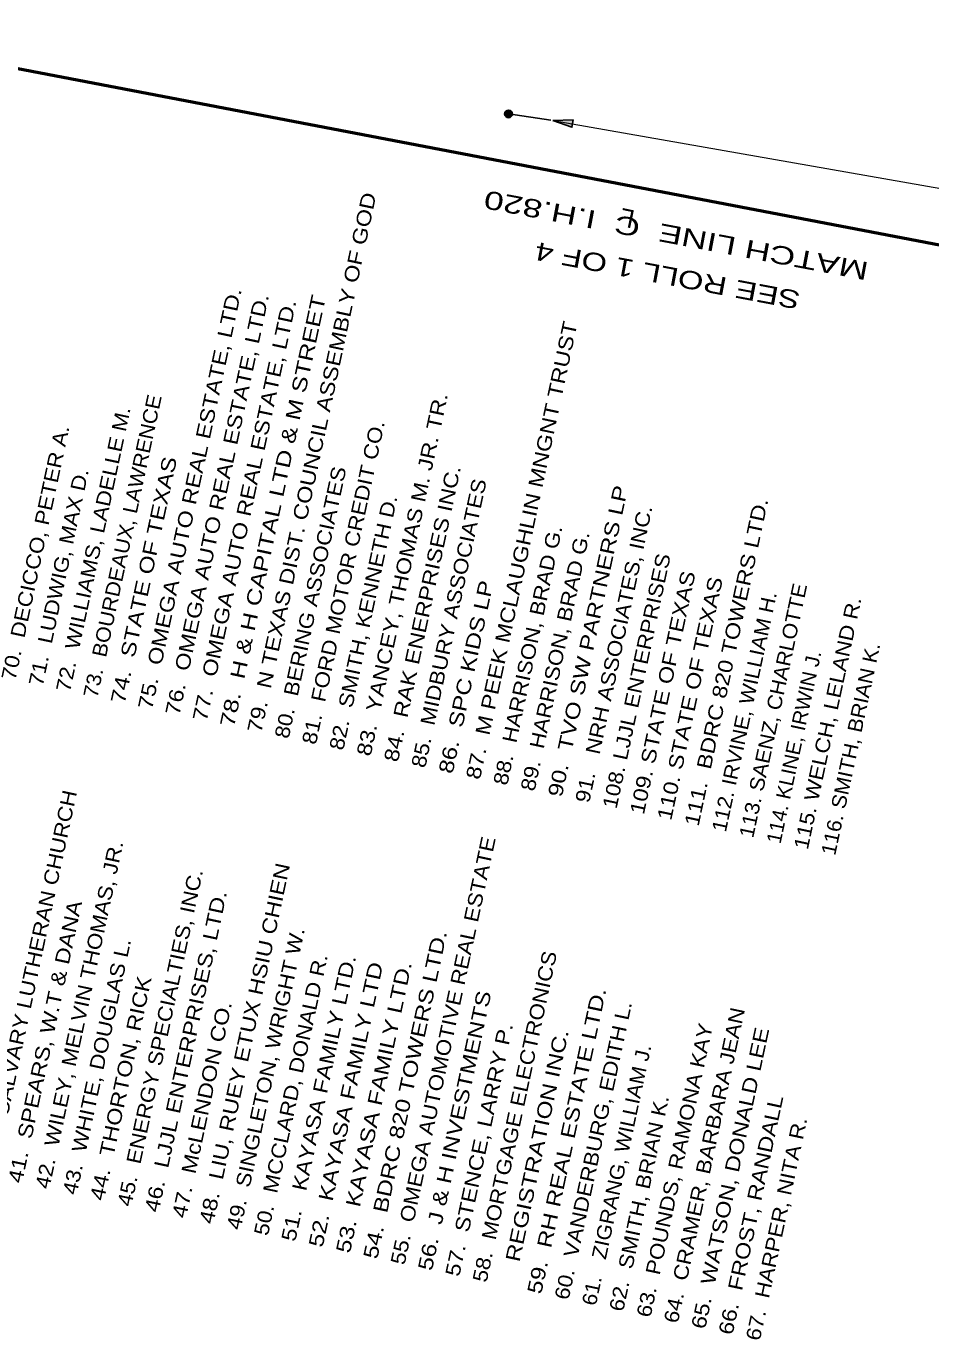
# Model space of a CAD drawing. Extents: x 2363411 to 2369702, y 6977197 to 6988655.
# Drawn here: x 2364093 to 2364967, y 6977941 to 6979210 of the extents above; entities that cross this region are included whole.
import ezdxf
from ezdxf.enums import TextEntityAlignment as Align

# ---------------------------------------------------------------- set-up
doc = ezdxf.new("R2010")
doc.units = 0
doc.header["$LTSCALE"] = 5.6
for name, color, linetype, lineweight in [('1', 7, 'Continuous', 25), ('18', 7, 'Continuous', 35), ('61', 7, 'Continuous', 25)]:
    doc.layers.add(name, color=color, linetype=linetype, lineweight=lineweight)

msp = doc.modelspace()

# ---------------------------------------------------------------- hatches: boundary and pattern name
at = {"layer": '1'}
for points in [[(2364561.269, 6979128.576, 1), (2364556.971, 6979122.474, 1)], [(2364602.052, 6979119.271), (2364620.433, 6979112.666), (2364621.582, 6979119.777)]]:
    msp.add_hatch(color=256, dxfattribs=at).paths.add_polyline_path(points)

# ---------------------------------------------------------------- linework, layer by layer
at = {"layer": '1', "lineweight": 53}
msp.add_line((2365678.349, 6978864.266), (2363870.127, 6979210.247), dxfattribs=at)
at = {"layer": '1'}
msp.add_line((2364559.12, 6979125.526), (2364599.897, 6979119.61), dxfattribs=at)
at = {"layer": '1', "lineweight": 13}
msp.add_line((2364602.343, 6979119.226), (2365303.581, 6978996.095), dxfattribs=at)
at = {"layer": '1'}
msp.add_lwpolyline([(2364602.052, 6979119.271), (2364620.433, 6979112.666), (2364621.582, 6979119.777)], close=True, dxfattribs=at)
msp.add_circle((2364559.12, 6979125.525), 3.732, dxfattribs=at)

# ---------------------------------------------------------------- texts
at = {"layer": '18'}
for s, width, p in [('79.  N TEXAS DIST. COUNCIL ASSEMBLY OF GOD', 1.2, (2364320.206, 6978526.494)), ('75.  OMEGA AUTO REAL ESTATE, LTD.', 1.2, (2364214.586, 6978549.062)), ('78.  H & H CAPITAL LTD & M STREET', 1.3, (2364293.801, 6978532.136)), ('76.  OMEGA AUTO REAL ESTATE, LTD.', 1.2, (2364240.991, 6978543.42)), ('77.  OMEGA AUTO REAL ESTATE, LTD.', 1.2, (2364267.396, 6978537.778)), ('87.  M PEEK MCLAUGHLIN MNGNT TRUST', 1.2, (2364531.446, 6978481.359)), ('73.  BOURDEAUX, LAWRENCE', 1.1, (2364161.776, 6978560.346)), ('83.  YANCEY, THOMAS M. JR. TR.', 1.2, (2364425.826, 6978503.927)), ('72.  WILLIAMS, LADELLE M.', 1.15, (2364135.371, 6978565.988)), ('81.  FORD MOTOR CREDIT CO.', 1.15, (2364373.016, 6978515.211)), ('70.  DECICCO, PETER A.', 1.15, (2364082.561, 6978577.272)), ('74.  STATE OF TEXAS', 1.25, (2364188.181, 6978554.704)), ('71.  LUDWIG, MAX D.', 1.15, (2364108.966, 6978571.63)), ('80.  BERING ASSOCIATES', 1.15, (2364346.611, 6978520.853)), ('84.  RAK ENERPRISES INC.', 1.2, (2364452.231, 6978498.285)), ('85.  MIDBURY ASSOCIATES', 1.15, (2364478.636, 6978492.643)), ('90.  TVO SW PARTNERS LP', 1.25, (2364610.661, 6978464.433)), ('82.  SMITH, KENNETH D.', 1.15, (2364399.421, 6978509.569)), ('111.  BDRC 820 TOWERS LTD.', 1.2, (2364742.686, 6978436.224)), ('91.   NRH ASSOCIATES, INC.', 1.15, (2364637.066, 6978458.792)), ('88.  HARRISON, BRAD G.', 1.15, (2364557.851, 6978475.717)), ('89.  HARRISON, BRAD G.', 1.15, (2364584.256, 6978470.075)), ('108. LJJL ENTERPRISES', 1.15, (2364663.471, 6978453.15)), ('86.  SPC KIDS LP', 1.25, (2364505.041, 6978487.001)), ('109. STATE OF TEXAS', 1.2, (2364689.876, 6978447.508)), ('110. STATE OF TEXAS', 1.2, (2364716.281, 6978441.866)), ('113. SAENZ, CHARLOTTE', 1.1, (2364795.496, 6978424.94)), ('112. IRVINE, WILLIAM H.', 1.1, (2364769.091, 6978430.582)), ('115. WELCH, LELAND R. ', 1.15, (2364848.306, 6978413.656)), ('116. SMITH, BRIAN K.', 1.1, (2364874.711, 6978408.014)), ('114. KLINE, IRWIN J.', 1.05, (2364821.901, 6978419.298)), ('40.1.  CALVARY LUTHERAN CHURCH', 1.15, (2364062.586, 6978096.875)), ('42.  WILEY, MELVIN THOMAS, JR.', 1.15, (2364115.396, 6978085.591)), ('55.  OMEGA AUTOMOTIVE REAL ESTATE', 1.15, (2364458.661, 6978012.246)), ('45.  ENERGY SPECIALTIES, INC.', 1.15, (2364194.611, 6978068.665)), ('48.  LIU, RUEY ETUX HSIU CHIEN', 1.2, (2364273.826, 6978051.74)), ('46.  LJJL ENTERPRISES, LTD. ', 1.2, (2364221.016, 6978063.023)), ('41.  SPEARS, W.T & DANA', 1.2, (2364088.991, 6978091.233)), ('49.  SINGLETON, WRIGHT W.', 1.15, (2364300.231, 6978046.098)), ('54.  BDRC 820 TOWERS LTD.', 1.25, (2364432.256, 6978017.888)), ('43.  WHITE, DOUGLAS L.', 1.15, (2364141.801, 6978079.949)), ('50.  MCCLARD, DONALD R.', 1.15, (2364326.636, 6978040.456)), ('51.   KAYASA FAMILY LTD.', 1.2, (2364353.041, 6978034.814)), ('52.  KAYASA FAMILY LTD', 1.25, (2364379.446, 6978029.172)), ('58.  MORTGAGE ELECTRONICS', 1.15, (2364537.876, 6977995.321)), ('44.  THORTON, RICK ', 1.2, (2364168.206, 6978074.307)), ('53.  KAYASA FAMILY LTD.', 1.25, (2364405.851, 6978023.53)), ('56.  J & H INVESTMENTS', 1.25, (2364485.066, 6978006.604)), ('59.  RH REAL ESTATE LTD.', 1.25, (2364590.686, 6977984.037)), ('47.  McLENDON CO.', 1.2, (2364247.421, 6978057.382)), ('60.  VANDERBURG, EDITH L.', 1.15, (2364617.091, 6977978.395)), ('64.  CRAMER, BARBARA JEAN', 1.15, (2364722.711, 6977955.827)), ('57.  STENCE, LARRY P. ', 1.2, (2364511.471, 6978000.962)), ('63.  POUNDS, RAMONA KAY', 1.15, (2364696.306, 6977961.469)), ('65.  WATSON, DONALD LEE ', 1.2, (2364749.116, 6977950.185)), ('    REGISTRATION INC.', 1.25, (2364564.281, 6977989.679)), ('61.   ZIGRANG, WILLIAM J.', 1.1, (2364643.496, 6977972.753)), ('62.  SMITH, BRIAN K.', 1.15, (2364669.901, 6977967.111)), ('66.  FROST, RANDALL ', 1.2, (2364775.521, 6977944.543)), ('67.  HARPER, NITA R.', 1.15, (2364801.926, 6977938.901))]:
    msp.add_text(s, height=14, rotation=77.939, dxfattribs=dict(at, width=width)).set_placement(p)
at = {"layer": '61'}
for s, rotation, width, p in [('MATCH LINE  C  I.H.820', 169.306, 1.45, (2364722.748, 6979016.786)), ('L', 167.939, 1.05, (2364675.554, 6979033.297)), ('SEE ROLL 1 OF 4', 169.306, 1.35, (2364714.411, 6978977.764))]:
    msp.add_text(s, height=17.5, rotation=rotation, dxfattribs=dict(at, width=width)).set_placement(p, align=Align.CENTER)

doc.saveas('drawing.dxf')
